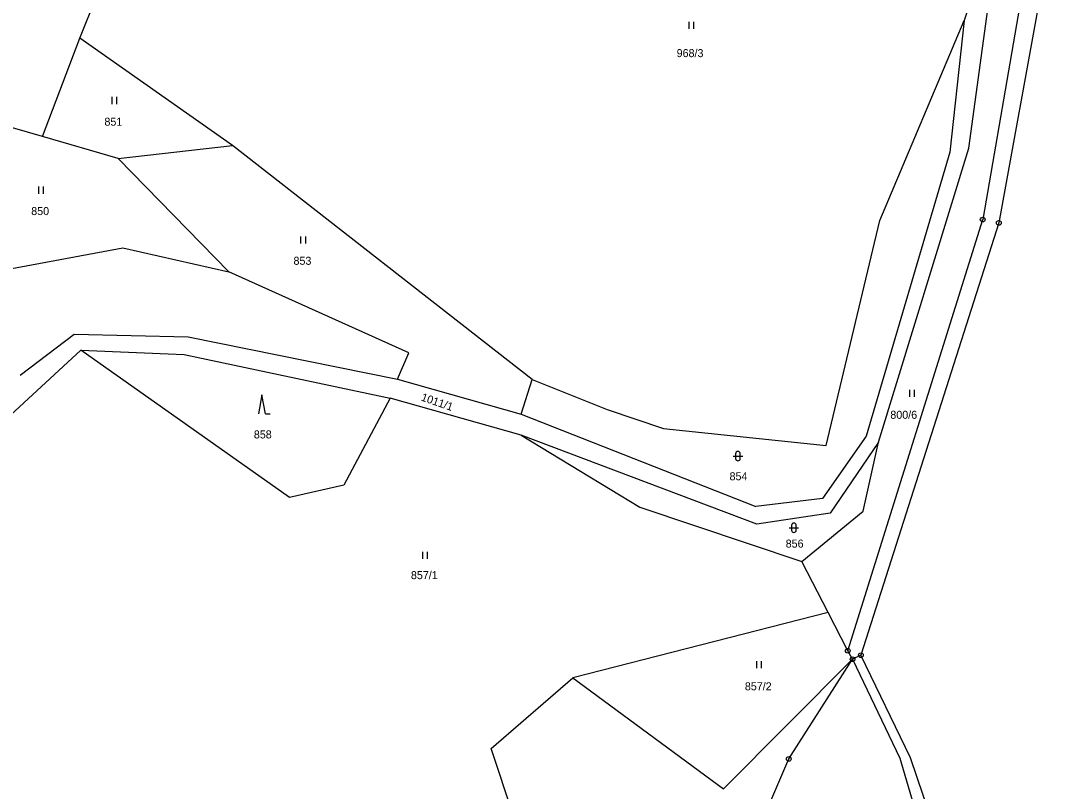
# Model space of a CAD drawing. Extents: x -754970 to -752637, y -970569 to -968179.
# Drawn here: x -753399.6 to -753182.2, y -969841.9 to -969678.2 of the extents above; entities that cross this region are included whole.
import ezdxf
from ezdxf.enums import TextEntityAlignment as Align

# ---------------------------------------------------------------- set-up
doc = ezdxf.new("R2010")
doc.units = 0
doc.header["$LTSCALE"] = 0.68
for name, color, linetype, lineweight in [('1', 7, 'Continuous', 25), ('3', 7, 'Continuous', 25), ('8', 7, 'Continuous', 25)]:
    doc.layers.add(name, color=color, linetype=linetype, lineweight=lineweight)
doc.layers.add('2', color=7, linetype='Continuous')

msp = doc.modelspace()

# ---------------------------------------------------------------- linework, layer by layer
at = {"layer": '1'}
for p, q in [((-753386.98, -969681.93), (-753375.58, -969653.2)), ((-753186.24, -969667.95), (-753195.3, -969720.48)), ((-753182.17, -969667.89), (-753191.87, -969721.17)), ((-753197.52, -969673.05), (-753199.21, -969678.21)), ((-753198.27, -969705.31), (-753193.96, -969674.27)), ((-753217.11, -969720.69), (-753199.21, -969678.21)), ((-753199.21, -969678.21), (-753202.3, -969706.15)), ((-753394.95, -969702.81), (-753386.98, -969681.93)), ((-753354.56, -969704.74), (-753386.98, -969681.93)), ((-753394.95, -969702.81), (-753418.44, -969696.08)), ((-753378.88, -969707.49), (-753394.95, -969702.81)), ((-753378.88, -969707.49), (-753354.56, -969704.74)), ((-753290.98, -969754.44), (-753354.56, -969704.74)), ((-753202.3, -969706.15), (-753220.02, -969766.44)), ((-753217.39, -969767.75), (-753198.27, -969705.31)), ((-753378.88, -969707.49), (-753355.38, -969731.56)), ((-753228.55, -969768.41), (-753217.11, -969720.69)), ((-753223.94, -969811.98), (-753195.3, -969720.48)), ((-753191.87, -969721.17), (-753221.16, -969812.94)), ((-753405.16, -969731.55), (-753377.88, -969726.48)), ((-753377.88, -969726.48), (-753355.38, -969731.56)), ((-753317.14, -969748.72), (-753355.38, -969731.56)), ((-753399.63, -969753.49), (-753388.19, -969744.77)), ((-753388.19, -969744.77), (-753364.01, -969745.34)), ((-753364.01, -969745.34), (-753319.58, -969754.34)), ((-753408.53, -969768.21), (-753386.79, -969748.17)), ((-753386.79, -969748.17), (-753364.85, -969749.09)), ((-753342.45, -969779.47), (-753386.79, -969748.17)), ((-753364.85, -969749.09), (-753321.07, -969758.38)), ((-753319.58, -969754.34), (-753317.14, -969748.72)), ((-753319.58, -969754.34), (-753293.32, -969761.75)), ((-753321.07, -969758.38), (-753330.92, -969776.85)), ((-753293.32, -969766.25), (-753321.07, -969758.38)), ((-753275.05, -969760.81), (-753263.05, -969764.84)), ((-753293.32, -969761.75), (-753243.46, -969781.35)), ((-753263.05, -969764.84), (-753228.55, -969768.41)), ((-753293.32, -969766.25), (-753268.11, -969781.54)), ((-753243.27, -969785.1), (-753293.32, -969766.25)), ((-753220.02, -969766.44), (-753229.3, -969779.66)), ((-753217.39, -969767.75), (-753227.7, -969782.76)), ((-753220.67, -969782.38), (-753217.39, -969767.75)), ((-753330.92, -969776.85), (-753342.45, -969779.47)), ((-753229.3, -969779.66), (-753243.46, -969781.35)), ((-753268.11, -969781.54), (-753233.71, -969793.07)), ((-753227.7, -969782.76), (-753243.27, -969785.1)), ((-753233.71, -969793.07), (-753220.67, -969782.38)), ((-753228.13, -969803.87), (-753233.71, -969793.07)), ((-753228.13, -969803.87), (-753282.32, -969817.71)), ((-753223.94, -969811.98), (-753228.13, -969803.87)), ((-753222.93, -969813.8), (-753223.94, -969811.98)), ((-753221.16, -969812.94), (-753222.93, -969813.8)), ((-753210.6, -969834.73), (-753221.16, -969812.94)), ((-753250.32, -969841.31), (-753222.93, -969813.8)), ((-753236.47, -969834.94), (-753222.93, -969813.8)), ((-753222.93, -969813.8), (-753212.9, -969834.82)), ((-753299.64, -969832.77), (-753282.32, -969817.71)), ((-753282.32, -969817.71), (-753250.32, -969841.31)), ((-753290.64, -969859.99), (-753299.64, -969832.77)), ((-753254.92, -969877.76), (-753236.47, -969834.94)), ((-753212.9, -969834.82), (-753206.76, -969855.56)), ((-753203.35, -969856.12), (-753210.6, -969834.73))]:
    msp.add_line(p, q, dxfattribs=at)
msp.add_lwpolyline([(-753293.32, -969761.75), (-753290.98, -969754.44), (-753275.05, -969760.81)], dxfattribs=at)
at = {"layer": '3'}
for p, q in [((-753257.631, -969679.98), (-753257.631, -969678.48)), ((-753256.63, -969679.98), (-753256.63, -969678.48)), ((-753380.131, -969695.95), (-753380.131, -969694.45)), ((-753379.13, -969695.95), (-753379.13, -969694.45)), ((-753395.681, -969714.98), (-753395.681, -969713.48)), ((-753394.68, -969714.98), (-753394.68, -969713.48)), ((-753340.041, -969725.56), (-753340.041, -969724.06)), ((-753339.04, -969725.56), (-753339.04, -969724.06)), ((-753210.751, -969758.1), (-753210.751, -969756.6)), ((-753209.75, -969758.1), (-753209.75, -969756.6)), ((-753347.57, -969761.7), (-753346.574, -969761.7)), ((-753248.261, -969770.671), (-753246.259, -969770.671)), ((-753247.761, -969770.171), (-753247.761, -969771.172)), ((-753246.759, -969771.172), (-753246.759, -969770.171)), ((-753236.381, -969785.891), (-753234.379, -969785.891)), ((-753235.881, -969785.391), (-753235.881, -969786.392)), ((-753234.879, -969786.392), (-753234.879, -969785.391)), ((-753314.191, -969792.46), (-753314.191, -969790.96)), ((-753313.19, -969792.46), (-753313.19, -969790.96)), ((-753243.261, -969815.67), (-753243.261, -969814.17)), ((-753242.26, -969815.67), (-753242.26, -969814.17))]:
    msp.add_line(p, q, dxfattribs=at)
msp.add_lwpolyline([(-753347.57, -969761.7), (-753348.32, -969757.7), (-753349.07, -969761.7)], dxfattribs=at)
for centre, start, end in [((-753247.26, -969770.1709), 0, 180), ((-753247.26, -969771.1709), 180, 359.98789), ((-753235.38, -969785.3909), 0, 180), ((-753235.38, -969786.3909), 180, 359.98789)]:
    msp.add_arc(centre, 0.5, start, end, dxfattribs=at)
at = {"layer": '8'}
for centre, radius in [((-753195.3, -969720.4799), 0.5), ((-753195.3, -969720.4799), 0.0303), ((-753191.87, -969721.1699), 0.5), ((-753191.87, -969721.1699), 0.0303), ((-753223.94, -969811.9799), 0.5), ((-753223.94, -969811.9799), 0.0303), ((-753222.93, -969813.7999), 0.5), ((-753221.16, -969812.9399), 0.5), ((-753221.16, -969812.9399), 0.0303), ((-753222.93, -969813.7999), 0.0303), ((-753236.47, -969834.9399), 0.5), ((-753236.47, -969834.9399), 0.0303)]:
    msp.add_circle(centre, radius, dxfattribs=at)

# ---------------------------------------------------------------- texts
at = {"layer": '2'}
for s, p in [('968/3', (-753257.43, -969685.985)), ('851', (-753379.869, -969700.545)), ('850', (-753395.419, -969719.515)), ('853', (-753339.729, -969730.065)), ('800/6', (-753212.06, -969762.755)), ('858', (-753348.149, -969766.925)), ('854', (-753247.149, -969775.805)), ('856', (-753235.229, -969790.095)), ('857/1', (-753313.85, -969796.795)), ('857/2', (-753242.95, -969820.385))]:
    msp.add_text(s, height=1.7, dxfattribs=at).set_placement(p, align=Align.CENTER)
msp.add_text('1011/1', height=1.7, rotation=341, dxfattribs=at).set_placement((-753311.3867, -969759.98), align=Align.CENTER)

doc.saveas('drawing.dxf')
